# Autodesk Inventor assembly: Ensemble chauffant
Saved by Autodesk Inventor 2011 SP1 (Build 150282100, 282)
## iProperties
Created: 2010-12
Part Number: Ensemble chauffant
Document SubType Name: Assembly
Designer: eric
Author: eric
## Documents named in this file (4)
- D:\eduinventor\maquettesaip2011\machineàpain\Workspace\Ensemble chauffant.iam
- D:\eduinventor\maquettesaip2011\machineàpain\Workspace\equerre de resistance.ipt
- D:\eduinventor\maquettesaip2011\machineàpain\Workspace\agrafe.ipt
- D:\eduinventor\maquettesaip2011\machineàpain\Workspace\support de resistance thermique.ipt
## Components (3 placed, 3 different names)
1. equerre de resistance:1
2. agrafe:1
3. support de resistance thermique:1
